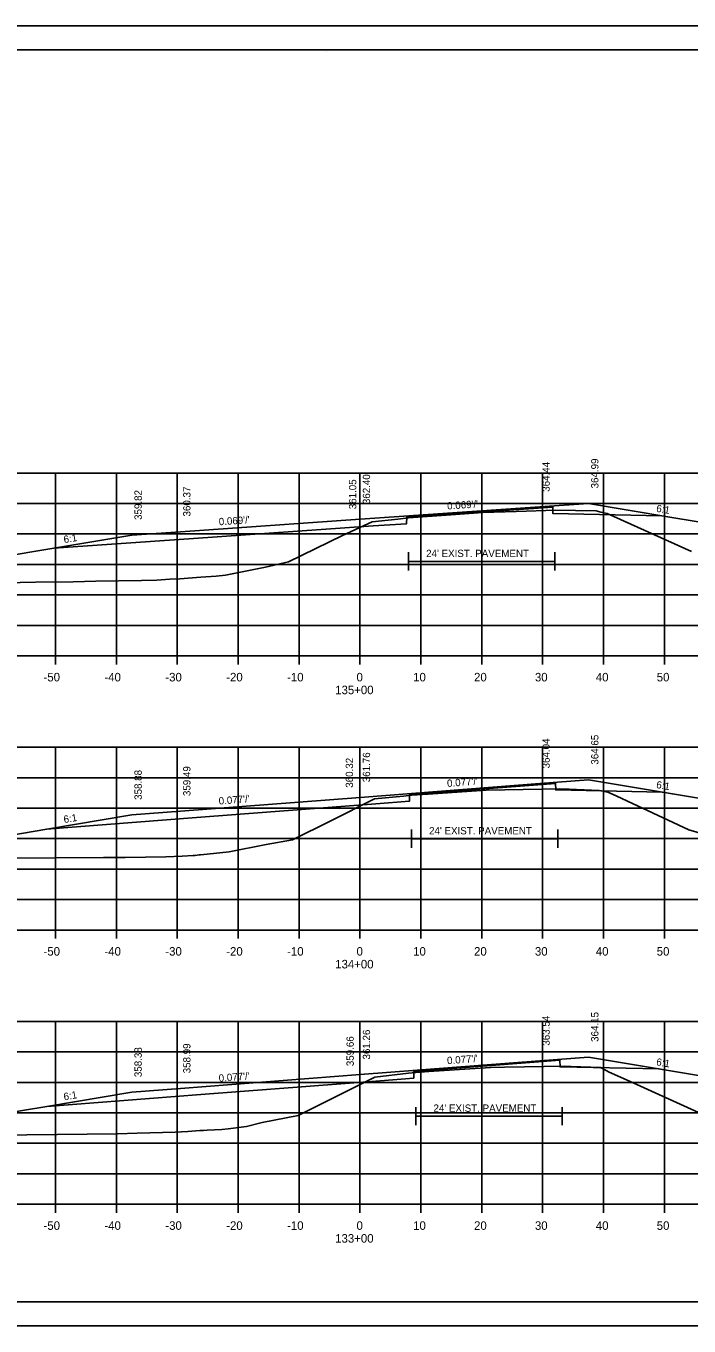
# Model space of a CAD drawing. Extents: x 1374859 to 1376773, y 382242 to 389804.
# Drawn here: x 1376079.7 to 1376188.6, y 385228.5 to 385441.8 of the extents above; entities that cross this region are included whole.
import ezdxf

# ---------------------------------------------------------------- set-up
doc = ezdxf.new("R2010")
doc.units = 0
for name, color, linetype in [('R_Axis', 7, 'Continuous'), ('R_Axis Annot', 7, 'Continuous'), ('R_Border', 7, 'Continuous'), ('R_Border Notes', 7, 'Continuous'), ('R_Exist Surface', 7, 'Continuous'), ('R_Fin Surface', 7, 'Continuous'), ('R_Grid', 7, 'Continuous'), ('R_No Plot', 7, 'Continuous'), ('R_Xsect Elev', 7, 'Continuous'), ('R_Xsect Slope', 7, 'Continuous')]:
    doc.layers.add(name, color=color, linetype=linetype)

msp = doc.modelspace()

# ---------------------------------------------------------------- linework, layer by layer
at = {"layer": 'R_Axis'}
for p, q in [((1375994.57, 385338.45), (1376274.57, 385338.45)), ((1376084.57, 385337.05), (1376084.57, 385338.45)), ((1376094.57, 385337.05), (1376094.57, 385338.45)), ((1376104.57, 385337.05), (1376104.57, 385338.45)), ((1376114.57, 385337.05), (1376114.57, 385338.45)), ((1376124.57, 385337.05), (1376124.57, 385338.45)), ((1376134.57, 385337.05), (1376134.57, 385338.45)), ((1376144.57, 385337.05), (1376144.57, 385338.45)), ((1376154.57, 385337.05), (1376154.57, 385338.45)), ((1376164.57, 385337.05), (1376164.57, 385338.45)), ((1376174.57, 385337.05), (1376174.57, 385338.45)), ((1376184.57, 385337.05), (1376184.57, 385338.45)), ((1375994.57, 385293.45), (1376274.57, 385293.45)), ((1376084.57, 385292.05), (1376084.57, 385293.45)), ((1376094.57, 385292.05), (1376094.57, 385293.45)), ((1376104.57, 385292.05), (1376104.57, 385293.45)), ((1376114.57, 385292.05), (1376114.57, 385293.45)), ((1376124.57, 385292.05), (1376124.57, 385293.45)), ((1376134.57, 385292.05), (1376134.57, 385293.45)), ((1376144.57, 385292.05), (1376144.57, 385293.45)), ((1376154.57, 385292.05), (1376154.57, 385293.45)), ((1376164.57, 385292.05), (1376164.57, 385293.45)), ((1376174.57, 385292.05), (1376174.57, 385293.45)), ((1376184.57, 385292.05), (1376184.57, 385293.45)), ((1375994.57, 385248.45), (1376274.57, 385248.45)), ((1376084.57, 385247.05), (1376084.57, 385248.45)), ((1376094.57, 385247.05), (1376094.57, 385248.45)), ((1376104.57, 385247.05), (1376104.57, 385248.45)), ((1376114.57, 385247.05), (1376114.57, 385248.45)), ((1376124.57, 385247.05), (1376124.57, 385248.45)), ((1376134.57, 385247.05), (1376134.57, 385248.45)), ((1376144.57, 385247.05), (1376144.57, 385248.45)), ((1376154.57, 385247.05), (1376154.57, 385248.45)), ((1376164.57, 385247.05), (1376164.57, 385248.45)), ((1376174.57, 385247.05), (1376174.57, 385248.45)), ((1376184.57, 385247.05), (1376184.57, 385248.45))]:
    msp.add_line(p, q, dxfattribs=at)
at = {"layer": 'R_Border'}
for p, q in [((1375976.57, 385437.91), (1376292.75, 385437.91)), ((1376129.09, 385437.65), (1376129.09, 385437.65)), ((1376129.09, 385437.65), (1376129.09, 385437.65)), ((1376292.75, 385232.45), (1375976.57, 385232.45))]:
    msp.add_line(p, q, dxfattribs=at)
at = {"layer": 'R_Border Notes'}
for points in [[(1376142.57, 385355.45), (1376142.57, 385352.45)], [(1376142.57, 385353.95), (1376166.57, 385353.95)], [(1376166.57, 385355.45), (1376166.57, 385352.45)], [(1376143.05, 385309.93), (1376143.05, 385306.93)], [(1376167.06, 385309.93), (1376167.06, 385306.93)], [(1376143.05, 385308.43), (1376167.06, 385308.43)], [(1376143.77, 385264.4), (1376143.77, 385261.4)], [(1376167.78, 385264.4), (1376167.78, 385261.4)], [(1376143.77, 385262.9), (1376167.78, 385262.9)]]:
    msp.add_lwpolyline(points, dxfattribs=at)
at = {"layer": 'R_Exist Surface'}
for points in [[(1376068.77, 385350.24), (1376081.29, 385350.51), (1376087.5, 385350.61), (1376091.2, 385350.7), (1376098.69, 385350.83), (1376101.2, 385350.89), (1376103.35, 385351.02), (1376104.97, 385351.07), (1376108.43, 385351.34), (1376110.95, 385351.54), (1376112.49, 385351.66), (1376119.06, 385352.99), (1376122.83, 385353.85), (1376131.71, 385358.17), (1376136.59, 385360.44), (1376140.81, 385360.89), (1376142.57, 385361.07), (1376149.49, 385361.58), (1376154.78, 385361.98), (1376160.2, 385362.14), (1376166.76, 385362.33), (1376169.96, 385362.29), (1376173.34, 385362.23), (1376174.12, 385362.04), (1376175.15, 385361.82), (1376189.02, 385355.56)], [(1376076.91, 385305.23), (1376092.44, 385305.34), (1376096.02, 385305.37), (1376102.67, 385305.45), (1376105.36, 385305.59), (1376107.16, 385305.69), (1376107.5, 385305.7), (1376107.82, 385305.72), (1376108.15, 385305.79), (1376108.4, 385305.78), (1376109.48, 385305.91), (1376113.09, 385306.26), (1376119.16, 385307.46), (1376123.5, 385308.27), (1376129.79, 385311.38), (1376136.96, 385314.96), (1376141.71, 385315.44), (1376143.05, 385315.58), (1376145.75, 385315.76), (1376155.28, 385316.39), (1376164.45, 385316.56), (1376167.39, 385316.62), (1376168.93, 385316.57), (1376173.85, 385316.37), (1376175.02, 385316.14), (1376175.16, 385316.12), (1376176.74, 385315.41), (1376188.61, 385309.91), (1376192.52, 385308.77)], [(1376076.78, 385259.8), (1376079.86, 385259.82), (1376094.78, 385259.99), (1376097.96, 385260.09), (1376104.25, 385260.29), (1376106.32, 385260.41), (1376108.28, 385260.53), (1376108.88, 385260.55), (1376109.5, 385260.58), (1376111.88, 385260.73), (1376112.92, 385260.85), (1376115.96, 385261.23), (1376118.52, 385261.84), (1376124.4, 385263.02), (1376133.61, 385267.63), (1376137.01, 385269.33), (1376142.57, 385269.94), (1376143.77, 385270.07), (1376145.9, 385270.22), (1376156.03, 385270.9), (1376158.3, 385270.94), (1376168.1, 385271.09), (1376169.24, 385271.05), (1376174.06, 385270.91), (1376174.99, 385270.41), (1376175.48, 385270.11), (1376178.83, 385268.64), (1376190.16, 385263.53)]]:
    msp.add_lwpolyline(points, dxfattribs=at)
at = {"layer": 'R_Fin Surface'}
for points in [[(1376045.72, 385350.21), (1376053.8, 385347.51), (1376075.09, 385354.61), (1376084.29, 385356.14), (1376097.09, 385358.27), (1376105.09, 385358.82), (1376134.59, 385360.86), (1376164.09, 385362.89), (1376172.09, 385363.44), (1376185.45, 385361.21), (1376194.09, 385359.77), (1376221.71, 385350.57)], [(1376084.29, 385356.14), (1376107.26, 385357.72), (1376136.74, 385359.76), (1376142.24, 385360.13), (1376142.25, 385361.21), (1376166.25, 385362.87), (1376166.26, 385361.79), (1376184.14, 385361.43)], [(1376049.29, 385304.98), (1376056.66, 385302.52), (1376075.09, 385308.66), (1376083.13, 385310), (1376097.09, 385312.33), (1376105.09, 385312.95), (1376134.59, 385315.22), (1376164.09, 385317.49), (1376172.09, 385318.1), (1376185.9, 385315.8), (1376194.09, 385314.44), (1376222.34, 385305.02)], [(1376083.1, 385310), (1376107.72, 385311.89), (1376137.2, 385314.17), (1376142.7, 385314.59), (1376142.71, 385315.67), (1376166.71, 385317.52), (1376166.72, 385316.44), (1376184.18, 385316.09)], [(1376051.43, 385259.78), (1376058.18, 385257.53), (1376075.09, 385263.16), (1376083.13, 385264.5), (1376097.09, 385266.83), (1376105.09, 385267.45), (1376134.59, 385269.72), (1376164.09, 385271.99), (1376172.09, 385272.6), (1376185.9, 385270.3), (1376194.09, 385268.94), (1376220.64, 385260.09)], [(1376083.13, 385264.5), (1376108.43, 385266.45), (1376137.91, 385268.72), (1376143.41, 385269.14), (1376143.42, 385270.23), (1376167.42, 385272.08), (1376167.43, 385270.99), (1376183.69, 385270.67)]]:
    msp.add_lwpolyline(points, dxfattribs=at)
at = {"layer": 'R_Grid'}
for p, q in [((1375994.57, 385368.45), (1376274.57, 385368.45)), ((1376084.57, 385338.45), (1376084.57, 385368.45)), ((1376094.57, 385338.45), (1376094.57, 385368.45)), ((1376104.57, 385338.45), (1376104.57, 385368.45)), ((1376114.57, 385338.45), (1376114.57, 385368.45)), ((1376124.57, 385338.45), (1376124.57, 385368.45)), ((1376134.57, 385338.45), (1376134.57, 385368.45)), ((1376144.57, 385338.45), (1376144.57, 385368.45)), ((1376154.57, 385338.45), (1376154.57, 385368.45)), ((1376164.57, 385338.45), (1376164.57, 385368.45)), ((1376174.57, 385338.45), (1376174.57, 385368.45)), ((1376184.57, 385338.45), (1376184.57, 385368.45)), ((1375994.57, 385363.45), (1376274.57, 385363.45)), ((1375994.57, 385358.45), (1376274.57, 385358.45)), ((1375994.57, 385353.45), (1376274.57, 385353.45)), ((1375994.57, 385348.45), (1376274.57, 385348.45)), ((1375994.57, 385343.45), (1376274.57, 385343.45)), ((1375994.57, 385338.45), (1376274.57, 385338.45)), ((1375994.57, 385323.45), (1376274.57, 385323.45)), ((1376084.57, 385293.45), (1376084.57, 385323.45)), ((1376094.57, 385293.45), (1376094.57, 385323.45)), ((1376104.57, 385293.45), (1376104.57, 385323.45)), ((1376114.57, 385293.45), (1376114.57, 385323.45)), ((1376124.57, 385293.45), (1376124.57, 385323.45)), ((1376134.57, 385293.45), (1376134.57, 385323.45)), ((1376144.57, 385293.45), (1376144.57, 385323.45)), ((1376154.57, 385293.45), (1376154.57, 385323.45)), ((1376164.57, 385293.45), (1376164.57, 385323.45)), ((1376174.57, 385293.45), (1376174.57, 385323.45)), ((1376184.57, 385293.45), (1376184.57, 385323.45)), ((1375994.57, 385318.45), (1376274.57, 385318.45)), ((1375994.57, 385313.45), (1376274.57, 385313.45)), ((1375994.57, 385308.45), (1376274.57, 385308.45)), ((1375994.57, 385303.45), (1376274.57, 385303.45)), ((1375994.57, 385298.45), (1376274.57, 385298.45)), ((1375994.57, 385293.45), (1376274.57, 385293.45)), ((1375994.57, 385278.45), (1376274.57, 385278.45)), ((1376084.57, 385248.45), (1376084.57, 385278.45)), ((1376094.57, 385248.45), (1376094.57, 385278.45)), ((1376104.57, 385248.45), (1376104.57, 385278.45)), ((1376114.57, 385248.45), (1376114.57, 385278.45)), ((1376124.57, 385248.45), (1376124.57, 385278.45)), ((1376134.57, 385248.45), (1376134.57, 385278.45)), ((1376144.57, 385248.45), (1376144.57, 385278.45)), ((1376154.57, 385248.45), (1376154.57, 385278.45)), ((1376164.57, 385248.45), (1376164.57, 385278.45)), ((1376174.57, 385248.45), (1376174.57, 385278.45)), ((1376184.57, 385248.45), (1376184.57, 385278.45)), ((1375994.57, 385273.45), (1376274.57, 385273.45)), ((1375994.57, 385268.45), (1376274.57, 385268.45)), ((1375994.57, 385263.45), (1376274.57, 385263.45)), ((1375994.57, 385258.45), (1376274.57, 385258.45)), ((1375994.57, 385253.45), (1376274.57, 385253.45)), ((1375994.57, 385248.45), (1376274.57, 385248.45))]:
    msp.add_line(p, q, dxfattribs=at)
at = {"layer": 'R_No Plot'}
for p, q in [((1375964.17, 385441.81), (1376297.5, 385441.81)), ((1375964.17, 385228.47), (1376297.5, 385228.47))]:
    msp.add_line(p, q, dxfattribs=at)
for points in [[(1375964.16, 385441.81), (1376297.5, 385441.81), (1376297.5, 385228.47), (1375964.16, 385228.47)], [(1376210.49, 385437.91), (1376210.49, 385428.03), (1376246.22, 385428.03), (1376246.22, 385425.11), (1376269.42, 385425.11), (1376269.42, 385400.78), (1376292.75, 385400.78), (1376292.75, 385232.45), (1375976.57, 385232.45), (1375976.57, 385437.91)]]:
    msp.add_lwpolyline(points, close=True, dxfattribs=at)

# ---------------------------------------------------------------- texts
at = {"layer": 'R_Axis Annot'}
for s, p in [('-50', (1376082.61, 385334.25)), ('-40', (1376092.61, 385334.25)), ('-30', (1376102.61, 385334.25)), ('-20', (1376112.61, 385334.25)), ('-10', (1376122.61, 385334.25)), ('0', (1376134.01, 385334.25)), ('10', (1376143.31, 385334.25)), ('20', (1376153.31, 385334.25)), ('30', (1376163.31, 385334.25)), ('40', (1376173.31, 385334.25)), ('50', (1376183.31, 385334.25)), ('135+00', (1376130.51, 385332.15)), ('-50', (1376082.61, 385289.25)), ('-40', (1376092.61, 385289.25)), ('-30', (1376102.61, 385289.25)), ('-20', (1376112.61, 385289.25)), ('-10', (1376122.61, 385289.25)), ('0', (1376134.01, 385289.25)), ('10', (1376143.31, 385289.25)), ('20', (1376153.31, 385289.25)), ('30', (1376163.31, 385289.25)), ('40', (1376173.31, 385289.25)), ('50', (1376183.31, 385289.25)), ('134+00', (1376130.51, 385287.15)), ('-50', (1376082.61, 385244.25)), ('-40', (1376092.61, 385244.25)), ('-30', (1376102.61, 385244.25)), ('-20', (1376112.61, 385244.25)), ('-10', (1376122.61, 385244.25)), ('0', (1376134.01, 385244.25)), ('10', (1376143.31, 385244.25)), ('20', (1376153.31, 385244.25)), ('30', (1376163.31, 385244.25)), ('40', (1376173.31, 385244.25)), ('50', (1376183.31, 385244.25)), ('133+00', (1376130.51, 385242.15))]:
    msp.add_text(s, height=1.4, dxfattribs=at).set_placement(p)
at = {"layer": 'R_Border Notes'}
for p in [(1376145.44, 385354.66), (1376145.92, 385309.14), (1376146.65, 385263.62)]:
    msp.add_text("24' EXIST. PAVEMENT", height=1.2, rotation=0, dxfattribs=at).set_placement(p)
at = {"layer": 'R_Xsect Elev'}
for s, p in [('364.44', (1376165.74, 385365.37)), ('364.99', (1376173.74, 385365.92)), ('361.05', (1376133.97, 385362.5)), ('362.40', (1376136.24, 385363.34)), ('359.82', (1376098.74, 385360.75)), ('360.37', (1376106.74, 385361.31)), ('364.04', (1376165.74, 385319.97)), ('364.65', (1376173.74, 385320.59)), ('361.76', (1376136.24, 385317.7)), ('359.49', (1376106.74, 385315.43)), ('360.32', (1376133.44, 385316.8)), ('358.88', (1376098.74, 385314.81)), ('363.54', (1376165.74, 385274.47)), ('364.15', (1376173.74, 385275.09)), ('359.66', (1376133.56, 385271.11)), ('361.26', (1376136.24, 385272.2)), ('358.38', (1376098.74, 385269.31)), ('358.99', (1376106.74, 385269.93))]:
    msp.add_text(s, height=1.2, rotation=90, dxfattribs=at).set_placement(p)
at = {"layer": 'R_Xsect Slope'}
for s, rotation, p in [("0.069'/'", 3.9399, (1376148.93, 385362.45)), ('6:1', 350.5358, (1376183.17, 385362.1)), ("0.069'/'", 3.9399, (1376111.43, 385359.86)), ('6:1', 9.4642, (1376086, 385356.93)), ("0.077'/'", 4.4031, (1376148.92, 385316.92)), ('6:1', 350.5358, (1376183.17, 385316.76)), ("0.077'/'", 4.4031, (1376111.42, 385314.03)), ('6:1', 9.4642, (1376086, 385310.99)), ("0.077'/'", 4.4031, (1376148.92, 385271.42)), ('6:1', 350.5358, (1376183.17, 385271.26)), ("0.077'/'", 4.4031, (1376111.42, 385268.54)), ('6:1', 9.4642, (1376086, 385265.49))]:
    msp.add_text(s, height=1.2, rotation=rotation, dxfattribs=at).set_placement(p)

doc.saveas('drawing.dxf')
